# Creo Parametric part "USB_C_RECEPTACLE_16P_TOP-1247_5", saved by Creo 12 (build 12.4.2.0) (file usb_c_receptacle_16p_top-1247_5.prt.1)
Units: Custom; MM, KILOGRAM, SECS

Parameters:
  PTC_WM_ITERATION = "0"
  PTC_WM_VERSION = "-.0"
  PTC_WM_LIFECYCLE_STATE = "In Work"
  PTC_WM_LIFECYCLE = "MO_CADDocument"
  PTC_WM_CREATED_BY = "Maximilian Roepper (Z0017RMS: MO)"
  PTC_WM_CREATED_ON = "18-Sep-26 11:36:42 AM"
  PTC_WM_MODIFIED_BY = "Maximilian Roepper (Z0017RMS: MO)"
  PTC_WM_MODIFIED_ON = "18-Sep-26 11:36:46 AM"
  PDMLINKNUMBER = "PDM000071454984"
  PTC_WM_NAME = "usb_c_receptacle_16p_top-1247_5.prt"
  PTC_WM_NUMBER = "PDM000071454984"

Other parameters: WEIGHT, WEIGHT_FACTOR, WEIGHT_ADD, _MASS_TEMP, _DIFF_TEMP, MC_ERRORS, SUPPLIER

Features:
  1. coordinate system
  2. datum plane "PRT_YZ"
  3. datum plane "PRT_XY"
  4. datum plane "PRT_XZ"
  5. coordinate system
  6. datum axis
  7. datum axis
  8. datum axis
  9. coordinate system
  10. imported feature
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
Other named items: PRT, SIEMENS_MO, DRW_VIEW_ORG, PRT_X, PRT_Y, PRT_Z, CS0, ROUGH_GROB

Layers: 00_STD_CSYS-KSYS, 01_STD_PLANES-EBENEN, 02_STD_AXES-ACHSEN, 03_STD_CSYS-KSYS, 24_IMPORT_FEAT-IMPORT_KE

Surfaces: 6 plane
